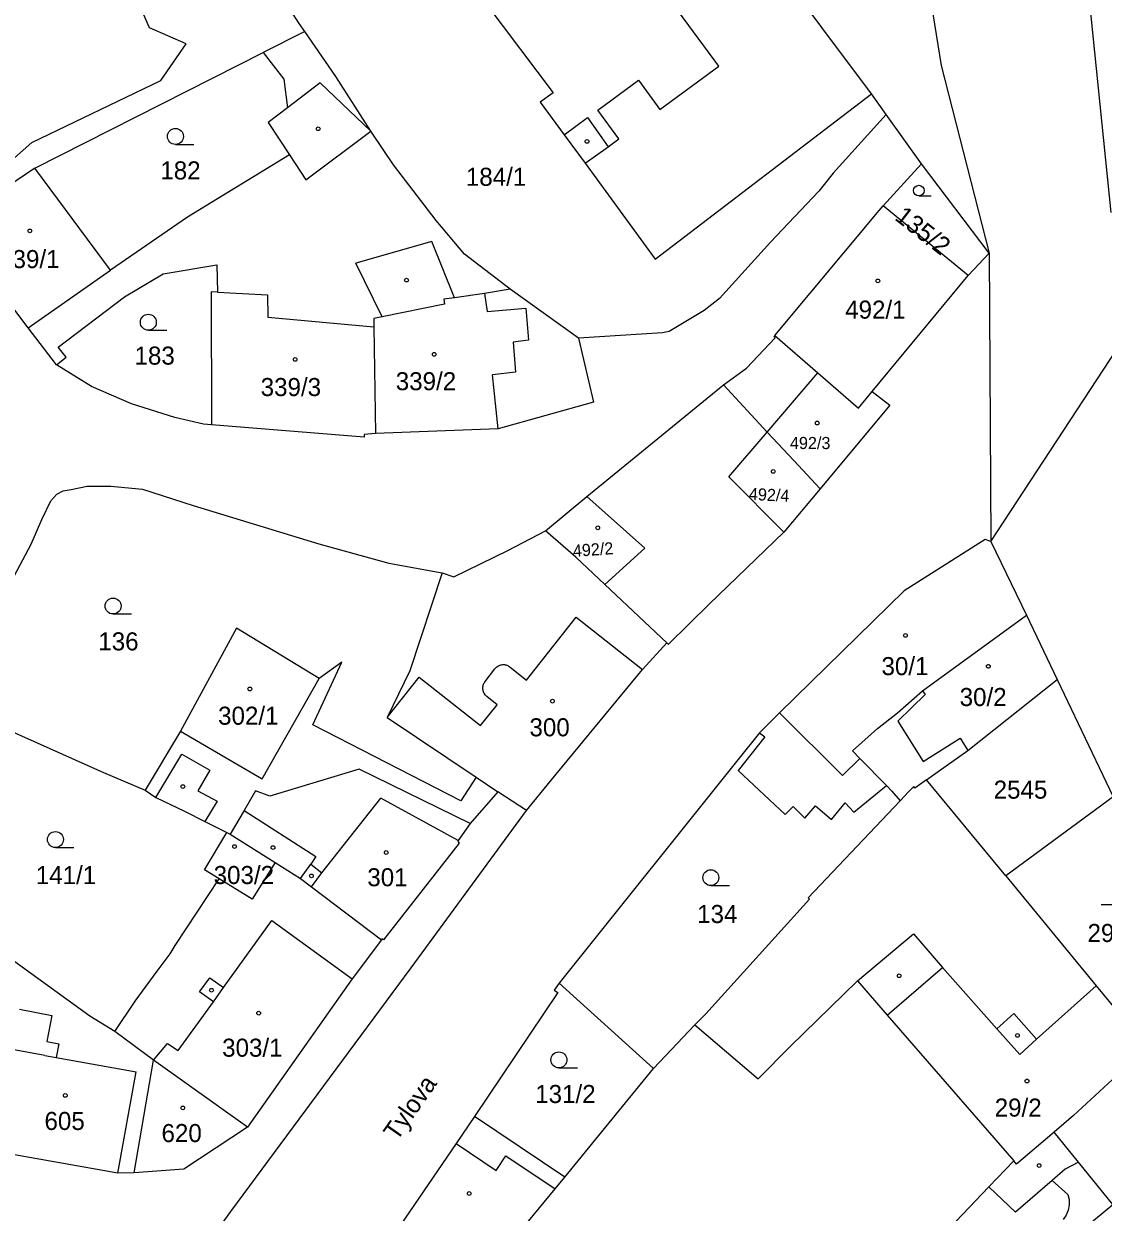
# Model space of a CAD drawing. Extents: x -679220 to -673243, y -1075091 to -1066557.
# Drawn here: x -676662.6 to -676560.9, y -1071294.6 to -1071182.6 of the extents above; entities that cross this region are included whole.
import ezdxf

# ---------------------------------------------------------------- set-up
doc = ezdxf.new("R2010")
doc.units = 0
for name, color, linetype in [('Hranice parcel', 7, 'Continuous'), ('Parcelní čísla', 7, 'Continuous'), ('Pop  PČ popisy', 7, 'Continuous'), ('Vnitřní kresba', 7, 'Continuous'), ('Značky budov', 7, 'Continuous'), ('Značky kultur', 7, 'Continuous')]:
    doc.layers.add(name, color=color, linetype=linetype)

msp = doc.modelspace()

# ---------------------------------------------------------------- linework, layer by layer
at = {"layer": 'Hranice parcel'}
for p, q in [((-676636.13, -1071183.38), (-676640.04, -1071185.36)), ((-676661.56, -1071196.25), (-676640.04, -1071185.36)), ((-676581.38, -1071191.18), (-676582.77, -1071189.23)), ((-676578.06, -1071195.82), (-676581.38, -1071191.18)), ((-676661.56, -1071196.25), (-676669.46, -1071201.6)), ((-676654.43, -1071205.84), (-676661.56, -1071196.25)), ((-676581.65, -1071199.8), (-676578.06, -1071195.82)), ((-676571.69, -1071204.25), (-676578.06, -1071195.82)), ((-676573.66, -1071206.34), (-676581.65, -1071199.8)), ((-676662.19, -1071211.28), (-676669.46, -1071201.6)), ((-676573.66, -1071206.34), (-676571.69, -1071204.25)), ((-676571.69, -1071204.25), (-676571.51, -1071231.38)), ((-676662.19, -1071211.28), (-676654.43, -1071205.84)), ((-676582.7, -1071217.26), (-676573.66, -1071206.34)), ((-676610.35, -1071212.26), (-676616.79, -1071207.63)), ((-676659.52, -1071214.75), (-676662.19, -1071211.28)), ((-676571.51, -1071231.38), (-676559.03, -1071212.34)), ((-676596.71, -1071216.63), (-676592.58, -1071221.09)), ((-676587.61, -1071226.45), (-676591.01, -1071230.53)), ((-676571.51, -1071231.38), (-676568.16, -1071238.33)), ((-676568.16, -1071238.33), (-676565.27, -1071244.39)), ((-676565.27, -1071244.39), (-676559.99, -1071255.44)), ((-676619.99, -1071253.6), (-676617.96, -1071254.98)), ((-676570.12, -1071262.88), (-676577.57, -1071253.84)), ((-676617.96, -1071254.98), (-676620.56, -1071257.95)), ((-676615.25, -1071256.73), (-676617.96, -1071254.98)), ((-676559.99, -1071255.44), (-676570.12, -1071262.88)), ((-676643.46, -1071258.79), (-676643.14, -1071258.95)), ((-676643.14, -1071258.95), (-676638.93, -1071261.62)), ((-676603.3, -1071281.02), (-676612.16, -1071272.99)), ((-676599.39, -1071276.9), (-676603.3, -1071281.02)), ((-676650.36, -1071280.25), (-676654.03, -1071277.54)), ((-676652.19, -1071290.84), (-676650.36, -1071280.25)), ((-676641.51, -1071286.53), (-676650.36, -1071280.25)), ((-676611.64, -1071291.25), (-676603.3, -1071281.02)), ((-676611.64, -1071291.25), (-676620.16, -1071285.53)), ((-676569.37, -1071289.71), (-676571.71, -1071292.17)), ((-676565.76, -1071291.56), (-676564.26, -1071292.87))]:
    msp.add_line(p, q, dxfattribs=at)
for points in [[(-676566.43, -1070961.91), (-676569.23, -1071023.51), (-676569.31, -1071051.96), (-676567.07, -1071105.14), (-676564.66, -1071149.4), (-676563.82, -1071164.93), (-676560.23, -1071200.41)], [(-676582.77, -1071189.23), (-676606.14, -1071157.99), (-676606.25, -1071158.07)], [(-676580.24, -1071158.83), (-676579.09, -1071168.64), (-676576.19, -1071186.56), (-676571.69, -1071204.25)], [(-676669.96, -1071200.75), (-676669.2, -1071200.31), (-676661.84, -1071193.82), (-676649.68, -1071187.97), (-676647.3, -1071184.53), (-676650.76, -1071183.01), (-676653.23, -1071177.35), (-676660.03, -1071176.21), (-676661.37, -1071172.06)], [(-676625.26, -1071172.51), (-676618.98, -1071180.87), (-676612.73, -1071189.14), (-676613.95, -1071190.03), (-676611.7, -1071193.1), (-676609.74, -1071195.78), (-676603.13, -1071204.8), (-676582.77, -1071189.23)], [(-676636.13, -1071183.38), (-676636.66, -1071182.62), (-676637.29, -1071181.65)], [(-676616.79, -1071207.63), (-676621.1, -1071204.35), (-676623.74, -1071201.17), (-676627.76, -1071195.93), (-676628.69, -1071194.59), (-676629.92, -1071192.77), (-676633.2, -1071187.62), (-676636.13, -1071183.38)], [(-676640.04, -1071185.36), (-676638.09, -1071187.86), (-676637.77, -1071190.55), (-676639.58, -1071191.93), (-676637.58, -1071194.98), (-676647.17, -1071200.84), (-676654.43, -1071205.84)], [(-676581.38, -1071191.18), (-676586.36, -1071196.71), (-676587.73, -1071198.39), (-676592.26, -1071203.21), (-676597.08, -1071208.52), (-676598.52, -1071209.65), (-676601.82, -1071211.62), (-676602.45, -1071211.74), (-676610.35, -1071212.26)], [(-676596.71, -1071216.63), (-676594.54, -1071215.08), (-676591.83, -1071212.21), (-676591.92, -1071212.13), (-676591.87, -1071211.99), (-676582.05, -1071200.23), (-676581.65, -1071199.8)], [(-676659.52, -1071214.75), (-676658.61, -1071214.05), (-676659.35, -1071213.08), (-676653.11, -1071208.37), (-676649.47, -1071206.18), (-676644.41, -1071205.33), (-676644.34, -1071207.93), (-676644.94, -1071207.9), (-676644.91, -1071220.41)], [(-676616.79, -1071207.63), (-676619.2, -1071208.05), (-676622.04, -1071208.44), (-676623.04, -1071208.58), (-676622.97, -1071209.04), (-676628.85, -1071210.25), (-676629.63, -1071210.41), (-676629.62, -1071211.17), (-676629.47, -1071221.24)], [(-676610.35, -1071212.26), (-676608.94, -1071218.26), (-676617.93, -1071220.79), (-676629.47, -1071221.24)], [(-676644.91, -1071220.41), (-676645.65, -1071220.34), (-676648.37, -1071219.71), (-676652.43, -1071218.42), (-676656.22, -1071216.81), (-676659.52, -1071214.75)], [(-676592.58, -1071221.09), (-676587.8, -1071215.52), (-676584, -1071218.83), (-676582.7, -1071217.26)], [(-676613.47, -1071230.38), (-676609.56, -1071227.17), (-676596.71, -1071216.63)], [(-676582.7, -1071217.26), (-676581.04, -1071218.56), (-676587.61, -1071226.45)], [(-676629.47, -1071221.24), (-676630.53, -1071221.33), (-676630.55, -1071221.58), (-676644.91, -1071220.41)], [(-676591.01, -1071230.53), (-676596.19, -1071225.3), (-676592.58, -1071221.09)], [(-676592.58, -1071221.09), (-676590.09, -1071223.77), (-676587.61, -1071226.45)], [(-676669.07, -1071246.91), (-676666.01, -1071239.77), (-676663.47, -1071234.59), (-676661.89, -1071231.66), (-676660.89, -1071229.31), (-676660.05, -1071227.58), (-676659.49, -1071226.94), (-676658.89, -1071226.62), (-676658.14, -1071226.49), (-676656.61, -1071226.19), (-676654.4, -1071226.19), (-676651.4, -1071226.48), (-676646.63, -1071228.01), (-676634.79, -1071231.61), (-676628.22, -1071233.43), (-676623.19, -1071234.33)], [(-676623.19, -1071234.33), (-676622.08, -1071234.73), (-676617.02, -1071232.24), (-676613.47, -1071230.38)], [(-676602.02, -1071240.93), (-676607.86, -1071235.43), (-676610.59, -1071232.86), (-676613.47, -1071230.38)], [(-676602.02, -1071240.93), (-676601.89, -1071241.05), (-676598.05, -1071237.3), (-676591.01, -1071230.53)], [(-676571.51, -1071231.38), (-676572.07, -1071231.2), (-676579.68, -1071236.05), (-676591.41, -1071247.54), (-676593.32, -1071249.4)], [(-676623.19, -1071234.33), (-676626.22, -1071243.58), (-676628.38, -1071247.98), (-676619.99, -1071253.6)], [(-676581.36, -1071254.38), (-676583.86, -1071251.82), (-676584.56, -1071251.11), (-676582.19, -1071249.01), (-676580.31, -1071247.52), (-676577.95, -1071245.45), (-676568.16, -1071238.33)], [(-676619.99, -1071253.6), (-676621.42, -1071255.81), (-676635.37, -1071248.66), (-676632.63, -1071242.75), (-676634.77, -1071244.3), (-676642.57, -1071239.57), (-676647.84, -1071249.24), (-676651.15, -1071254.81)], [(-676615.25, -1071256.73), (-676612.89, -1071253.85), (-676604.33, -1071243.46), (-676602.02, -1071240.93)], [(-676577.57, -1071253.84), (-676576.48, -1071253.05), (-676573.69, -1071251.06), (-676565.27, -1071244.39)], [(-676669.07, -1071246.91), (-676655.09, -1071253.14), (-676651.15, -1071254.81)], [(-676593.32, -1071249.4), (-676595.34, -1071251.94), (-676611.83, -1071272.55), (-676612.16, -1071272.99)], [(-676593.32, -1071249.4), (-676592.82, -1071249.8), (-676595.33, -1071252.96), (-676590.9, -1071257.09), (-676590.14, -1071256.34), (-676589.04, -1071257.45), (-676588.04, -1071256.28), (-676586.53, -1071257.56), (-676585.23, -1071256.01), (-676584.42, -1071256.88), (-676581.36, -1071254.38)], [(-676620.56, -1071257.95), (-676631.01, -1071252.83), (-676639.42, -1071255.38), (-676640.76, -1071254.88), (-676641.83, -1071256.71), (-676643.14, -1071258.95)], [(-676577.57, -1071253.84), (-676578.68, -1071254.63), (-676578.79, -1071254.45), (-676579.27, -1071254.98), (-676580.07, -1071255.8)], [(-676651.15, -1071254.81), (-676650.14, -1071255.51), (-676647.45, -1071256.8), (-676645.55, -1071257.77), (-676643.46, -1071258.79)], [(-676581.36, -1071254.38), (-676580.86, -1071254.89), (-676580.07, -1071255.8)], [(-676580.07, -1071255.8), (-676588.74, -1071264.94), (-676588.6, -1071265.07), (-676598.37, -1071275.88), (-676599.39, -1071276.9)], [(-676653.49, -1071309.92), (-676646.86, -1071299.89), (-676646.53, -1071300.11), (-676645.28, -1071298.13), (-676645.57, -1071297.94), (-676643.09, -1071294.48), (-676626.12, -1071271.55), (-676615.25, -1071256.73)], [(-676620.56, -1071257.95), (-676621.67, -1071259.56), (-676621.72, -1071259.65), (-676621.58, -1071259.79), (-676628.71, -1071268.9), (-676628.85, -1071268.77), (-676628.9, -1071268.91)], [(-676644.19, -1071263.17), (-676645.58, -1071262.32), (-676643.46, -1071258.79)], [(-676638.93, -1071261.62), (-676641.07, -1071265.08), (-676644.19, -1071263.17)], [(-676638.93, -1071261.62), (-676636.53, -1071263.14), (-676635.48, -1071263.91), (-676628.9, -1071268.91)], [(-676654.03, -1071277.54), (-676656.36, -1071276.08), (-676663.44, -1071270.99), (-676665.46, -1071269.41), (-676670.24, -1071265.95), (-676675.13, -1071262.42)], [(-676654.03, -1071277.54), (-676652.09, -1071274.67), (-676650.02, -1071271.85), (-676648.81, -1071270.23), (-676648.32, -1071269.45), (-676644.19, -1071263.17)], [(-676570.12, -1071262.88), (-676561.6, -1071273.23), (-676556.8, -1071279.05)], [(-676628.9, -1071268.91), (-676631.65, -1071272.57), (-676641.51, -1071286.53)], [(-676599.39, -1071276.9), (-676593.42, -1071281.98), (-676590.42, -1071278.95), (-676584.08, -1071272.78), (-676581.29, -1071275.99), (-676569.37, -1071289.71)], [(-676612.16, -1071272.99), (-676612.64, -1071273.63), (-676612.3, -1071273.85), (-676620.16, -1071285.53)], [(-676556.8, -1071279.05), (-676563.75, -1071285.45), (-676565.56, -1071287), (-676569.1, -1071290.02), (-676569.37, -1071289.71)], [(-676620.16, -1071285.53), (-676621.88, -1071288.09), (-676628.91, -1071298.37)], [(-676641.51, -1071286.53), (-676647.53, -1071290.5), (-676652.19, -1071290.84)], [(-676652.19, -1071290.84), (-676653.74, -1071290.88), (-676665.43, -1071288.8), (-676665.4, -1071288.65)], [(-676560.64, -1071299), (-676563.29, -1071296.53), (-676560.04, -1071293.83), (-676563.26, -1071289.85), (-676564.53, -1071290.49), (-676565.76, -1071291.56)], [(-676621.57, -1071303.28), (-676612.54, -1071292.35), (-676611.64, -1071291.25)], [(-676565.76, -1071291.56), (-676569.21, -1071294.54), (-676571.71, -1071292.17)], [(-676571.71, -1071292.17), (-676576.03, -1071296.71), (-676582.53, -1071302.89)], [(-676564.26, -1071292.87), (-676564.15, -1071293.36), (-676564.14, -1071293.86), (-676564.14, -1071293.87), (-676564.23, -1071294.37), (-676564.42, -1071294.83), (-676564.7, -1071295.25)]]:
    msp.add_lwpolyline(points, dxfattribs=at)
at = {"layer": 'Vnitřní kresba'}
for p, q in [((-676597.15, -1071186.62), (-676608.23, -1071171.61)), ((-676602.68, -1071190.7), (-676597.15, -1071186.62)), ((-676634.68, -1071188.19), (-676637.77, -1071190.55)), ((-676629.92, -1071192.77), (-676634.68, -1071188.19)), ((-676608.54, -1071190.78), (-676604.71, -1071187.95)), ((-676604.71, -1071187.95), (-676602.68, -1071190.7)), ((-676606.54, -1071193.49), (-676608.54, -1071190.78)), ((-676611.7, -1071193.1), (-676609.5, -1071191.48)), ((-676609.5, -1071191.48), (-676607.55, -1071194.22)), ((-676636.02, -1071197.34), (-676629.92, -1071192.77)), ((-676609.74, -1071195.78), (-676607.55, -1071194.22)), ((-676607.55, -1071194.22), (-676606.54, -1071193.49)), ((-676637.58, -1071194.98), (-676636.02, -1071197.34)), ((-676624.16, -1071203.14), (-676631.31, -1071205.17)), ((-676622.04, -1071208.44), (-676624.16, -1071203.14)), ((-676628.85, -1071210.25), (-676631.31, -1071205.17)), ((-676644.34, -1071207.93), (-676639.64, -1071208.17)), ((-676639.64, -1071208.17), (-676639.62, -1071210.28)), ((-676619.2, -1071208.05), (-676618.96, -1071209.74)), ((-676618.96, -1071209.74), (-676615.31, -1071209.43)), ((-676615.31, -1071209.43), (-676615.05, -1071212.43)), ((-676639.62, -1071210.28), (-676629.62, -1071211.17)), ((-676615.05, -1071212.43), (-676616.52, -1071212.61)), ((-676591.87, -1071211.99), (-676587.8, -1071215.52)), ((-676616.52, -1071212.61), (-676616.28, -1071215.46)), ((-676616.28, -1071215.46), (-676618.44, -1071215.71)), ((-676617.93, -1071220.79), (-676618.44, -1071215.71)), ((-676609.56, -1071227.17), (-676604.1, -1071232.01)), ((-676604.1, -1071232.01), (-676607.86, -1071235.43)), ((-676615.25, -1071244.45), (-676610.58, -1071238.53)), ((-676610.58, -1071238.53), (-676604.33, -1071243.46)), ((-676619.15, -1071244.58), (-676618.22, -1071243.38)), ((-676616.8, -1071243.22), (-676615.25, -1071244.45)), ((-676640.14, -1071253.73), (-676634.77, -1071244.3)), ((-676628.38, -1071247.98), (-676625.36, -1071244.16)), ((-676625.36, -1071244.16), (-676619.57, -1071248.73)), ((-676618.02, -1071246.76), (-676618.99, -1071245.99)), ((-676580.27, -1071248.31), (-676577.71, -1071245.8)), ((-676577.95, -1071245.45), (-676577.71, -1071245.8)), ((-676619.57, -1071248.73), (-676618.02, -1071246.76)), ((-676591.41, -1071247.54), (-676585.5, -1071253.42)), ((-676647.84, -1071249.24), (-676640.14, -1071253.73)), ((-676580.27, -1071248.31), (-676577.9, -1071252.11)), ((-676577.9, -1071252.11), (-676574.4, -1071249.92)), ((-676574.4, -1071249.92), (-676573.69, -1071251.06)), ((-676650.14, -1071255.51), (-676647.71, -1071251.43)), ((-676647.71, -1071251.43), (-676645.06, -1071252.93)), ((-676585.5, -1071253.42), (-676583.86, -1071251.82)), ((-676645.06, -1071252.93), (-676646.19, -1071254.86)), ((-676646.19, -1071254.86), (-676644.38, -1071255.86)), ((-676644.38, -1071255.86), (-676645.55, -1071257.77)), ((-676634.52, -1071262.6), (-676628.96, -1071255.57)), ((-676621.67, -1071259.56), (-676628.96, -1071255.57)), ((-676641.83, -1071256.71), (-676635.08, -1071261.07)), ((-676635.08, -1071261.07), (-676635.55, -1071261.79)), ((-676636.53, -1071263.14), (-676635.55, -1071261.79)), ((-676635.55, -1071261.79), (-676634.52, -1071262.6)), ((-676635.48, -1071263.91), (-676634.52, -1071262.6)), ((-676643.78, -1071273.39), (-676639.23, -1071267.08)), ((-676639.23, -1071267.08), (-676631.65, -1071272.57)), ((-676584.08, -1071272.78), (-676578.82, -1071268.33)), ((-676578.82, -1071268.33), (-676576.09, -1071271.5)), ((-676581.29, -1071275.99), (-676576.09, -1071271.5)), ((-676576.09, -1071271.5), (-676570.95, -1071277.27)), ((-676646.04, -1071273.81), (-676645.08, -1071272.48)), ((-676645.08, -1071272.48), (-676643.78, -1071273.39)), ((-676644.73, -1071274.73), (-676646.04, -1071273.81)), ((-676644.73, -1071274.73), (-676643.78, -1071273.39)), ((-676561.6, -1071273.23), (-676567.21, -1071278.26)), ((-676648.06, -1071279.34), (-676644.73, -1071274.73)), ((-676662.99, -1071275.43), (-676659.94, -1071276.02)), ((-676659.94, -1071276.02), (-676660.42, -1071278.48)), ((-676569.35, -1071275.85), (-676570.95, -1071277.27)), ((-676567.21, -1071278.26), (-676569.35, -1071275.85)), ((-676570.95, -1071277.27), (-676568.8, -1071279.69)), ((-676660.42, -1071278.48), (-676659.29, -1071278.7)), ((-676567.21, -1071278.26), (-676568.8, -1071279.69)), ((-676660.6, -1071279.79), (-676663.68, -1071279.22)), ((-676659.29, -1071278.7), (-676659.54, -1071279.98)), ((-676650.36, -1071280.25), (-676649.04, -1071278.66)), ((-676649.04, -1071278.66), (-676648.06, -1071279.34)), ((-676660.6, -1071279.79), (-676659.54, -1071279.98)), ((-676659.54, -1071279.98), (-676652, -1071281.32)), ((-676653.74, -1071290.88), (-676652, -1071281.32)), ((-676563.26, -1071289.85), (-676565.56, -1071287)), ((-676621.88, -1071288.09), (-676618.09, -1071290.62)), ((-676618.09, -1071290.62), (-676617.18, -1071289.25)), ((-676617.18, -1071289.25), (-676612.54, -1071292.35))]:
    msp.add_line(p, q, dxfattribs=at)
for points in [[(-676618.22, -1071243.38), (-676618.17, -1071243.31), (-676618.11, -1071243.26), (-676618.04, -1071243.2), (-676617.98, -1071243.15), (-676617.9, -1071243.11), (-676617.83, -1071243.07), (-676617.75, -1071243.04), (-676617.67, -1071243.02), (-676617.59, -1071243), (-676617.5, -1071242.99), (-676617.42, -1071242.99), (-676617.33, -1071242.99), (-676617.25, -1071243.01), (-676617.17, -1071243.02), (-676617.09, -1071243.05), (-676617.01, -1071243.08), (-676616.94, -1071243.12), (-676616.87, -1071243.17), (-676616.8, -1071243.22)], [(-676619.15, -1071244.58), (-676619.2, -1071244.65), (-676619.25, -1071244.72), (-676619.29, -1071244.79), (-676619.32, -1071244.87), (-676619.35, -1071244.95), (-676619.37, -1071245.03), (-676619.38, -1071245.11), (-676619.38, -1071245.19), (-676619.38, -1071245.28), (-676619.37, -1071245.36), (-676619.36, -1071245.44), (-676619.33, -1071245.52), (-676619.3, -1071245.6), (-676619.26, -1071245.68), (-676619.22, -1071245.75), (-676619.17, -1071245.82), (-676619.12, -1071245.88), (-676619.06, -1071245.94), (-676618.99, -1071245.99)]]:
    msp.add_lwpolyline(points, dxfattribs=at)
at = {"layer": 'Značky budov'}
for centre in [(-676634.86, -1071192.53), (-676609.55, -1071193.72), (-676662.01, -1071202.15), (-676626.55, -1071206.78), (-676582.16, -1071206.86), (-676623.94, -1071213.77), (-676637.04, -1071214.25), (-676587.87, -1071220.24), (-676592.01, -1071224.8), (-676608.54, -1071230.11), (-676579.57, -1071240.24), (-676571.76, -1071243.15), (-676641.3, -1071245.28), (-676612.81, -1071246.43), (-676647.61, -1071254.47), (-676642.74, -1071260.12), (-676639.12, -1071260.22), (-676628.46, -1071260.68), (-676635.5, -1071262.88), (-676580.15, -1071272.29), (-676644.91, -1071273.65), (-676640.47, -1071275.81), (-676569.02, -1071277.91), (-676568.12, -1071282.2), (-676658.68, -1071283.56), (-676647.62, -1071284.73), (-676566.98, -1071290.16), (-676620.64, -1071292.79)]:
    msp.add_circle(centre, 0.175, dxfattribs=at)
at = {"layer": 'Značky kultur'}
for p, q in [((-676648.31, -1071194), (-676646.56, -1071194)), ((-676578.31, -1071198.85), (-676577.13, -1071198.85)), ((-676650.86, -1071211.5), (-676649.11, -1071211.5)), ((-676654.18, -1071238.22), (-676652.43, -1071238.22)), ((-676659.61, -1071260.21), (-676657.86, -1071260.21)), ((-676597.89, -1071263.8), (-676596.14, -1071263.8)), ((-676561.13, -1071265.57), (-676560.13, -1071265.57)), ((-676612.2, -1071280.96), (-676610.45, -1071280.96))]:
    msp.add_line(p, q, dxfattribs=at)
for centre, radius in [((-676648.31, -1071193.25), 0.75), ((-676578.31, -1071198.35), 0.502), ((-676650.86, -1071210.75), 0.75), ((-676654.18, -1071237.47), 0.75), ((-676659.61, -1071259.46), 0.75), ((-676597.89, -1071263.05), 0.75), ((-676612.2, -1071280.21), 0.75)]:
    msp.add_circle(centre, radius, dxfattribs=at)

# ---------------------------------------------------------------- texts
at = {"layer": 'Parcelní čísla'}
for s, height, p in [('182', 1.7, (-676649.73, -1071197.3)), ('184/1', 1.7, (-676620.96, -1071197.9)), ('339/1', 1.7, (-676664.91, -1071205.65)), ('492/1', 1.7, (-676585.24, -1071210.41)), ('183', 1.7, (-676652.16, -1071214.74)), ('339/2', 1.7, (-676627.56, -1071217.15)), ('339/3', 1.7, (-676640.28, -1071217.7)), ('492/3', 1.139, (-676590.44, -1071222.69)), ('136', 1.7, (-676655.57, -1071241.65)), ('30/1', 1.7, (-676581.82, -1071243.98)), ('30/2', 1.7, (-676574.46, -1071246.89)), ('302/1', 1.7, (-676644.29, -1071248.65)), ('300', 1.7, (-676614.97, -1071249.74)), ('2545', 1.7, (-676571.26, -1071255.61)), ('141/1', 1.7, (-676661.46, -1071263.66)), ('303/2', 1.7, (-676644.71, -1071263.65)), ('301', 1.7, (-676630.24, -1071263.86)), ('134', 1.7, (-676599.18, -1071267.32)), ('29/1', 1.7, (-676562.42, -1071269.11)), ('303/1', 1.7, (-676643.91, -1071279.91)), ('131/2', 1.7, (-676614.43, -1071284.27)), ('29/2', 1.7, (-676571.16, -1071285.55)), ('605', 1.7, (-676660.64, -1071286.81)), ('620', 1.7, (-676649.62, -1071287.95))]:
    msp.add_text(s, height=height, dxfattribs=at).set_placement(p)
for s, height, rotation, p in [('135/2', 1.7, 322, (-676580.67, -1071201.03)), ('492/4', 1.139, 357, (-676594.33, -1071227.47)), ('492/2', 1.139, 4, (-676610.84, -1071232.85))]:
    msp.add_text(s, height=height, rotation=rotation, dxfattribs=at).set_placement(p)
at = {"layer": 'Pop  PČ popisy'}
msp.add_text('Tylova', height=1.7, rotation=55, dxfattribs=at).set_placement((-676627.45, -1071287.92))

doc.saveas('drawing.dxf')
